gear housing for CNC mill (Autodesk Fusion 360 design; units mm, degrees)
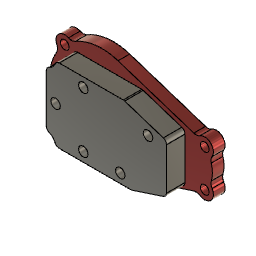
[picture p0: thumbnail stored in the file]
description: Gear Housing Assembly
derived_base_feature "Derived Base Feature1"
derived_base_feature "Derived Base Feature1" bodies "Front Housing"
derived_base_feature "Derived Base Feature1" bodies "Front Cover"
derived_base_feature "Derived Base Feature1" bodies "Back Housing"
as_built_joint "As-built1"
offset_faces "OffsetFaces1" distance 5
delete_face "DeleteFace1"
delete_face "DeleteFace2"
sketch "Sketch1" plane through (0, -21, 0) normal (0, -1, 0) x axis (1, 0, 0)
  line L1 (11.1724, 34.2225) -> (63.2283, 17.2281)
  line L2 (63.2283, -17.2281) -> (11.1724, -34.2225)
  arc A1 centre (64.7801, 21.9812) radius 5 clockwise from (67.4836, 17.7752) to (63.2283, 17.2281)
  arc A2 centre (0, 0) radius 36 clockwise from (-18.189, 31.067) to (11.1724, 34.2225)
  arc A3 centre (-20.7152, 35.3819) radius 5 clockwise from (-18.189, 31.067) to (-22.8701, 30.8701)
  arc A4 centre (-25.4558, 25.4558) radius 6 clockwise from (-30.8701, 22.8701) to (-22.8701, 30.8701)
  arc A5 centre (-35.3819, 20.7152) radius 5 clockwise from (-30.8701, 22.8701) to (-31.067, 18.189)
  arc A6 centre (0, 0) radius 36 clockwise from (-31.067, -18.189) to (-31.067, 18.189)
  arc A7 centre (-35.3819, -20.7152) radius 5 clockwise from (-31.067, -18.189) to (-30.8701, -22.8701)
  arc A8 centre (-25.4558, -25.4558) radius 6 clockwise from (-22.8701, -30.8701) to (-30.8701, -22.8701)
  arc A9 centre (-20.7152, -35.3819) radius 5 clockwise from (-22.8701, -30.8701) to (-18.189, -31.067)
  arc A10 centre (0, 0) radius 36 clockwise from (11.1724, -34.2225) to (-18.189, -31.067)
  arc A11 centre (64.7801, -21.9812) radius 5 clockwise from (63.2283, -17.2281) to (67.4836, -17.7752)
  arc A12 centre (70.7279, -12.7279) radius 6 clockwise from (75.774, -9.4818) to (67.4836, -17.7752)
  arc A13 centre (79.979, -6.7767) radius 5 clockwise from (75.774, -9.4818) to (75.201, -5.3035)
  arc A14 centre (58, 0) radius 18 clockwise from (75.201, 5.3035) to (75.201, -5.3035)
  arc A15 centre (79.979, 6.7767) radius 5 clockwise from (75.201, 5.3035) to (75.774, 9.4818)
  arc A16 centre (70.7279, 12.7279) radius 6 clockwise from (67.4836, 17.7752) to (75.774, 9.4818)
  circle C1 centre (70.7279, -12.7279) radius 3
  circle C2 centre (70.7279, 12.7279) radius 3
  circle C3 centre (-25.4558, -25.4558) radius 3
  circle C4 centre (-25.4558, 25.4558) radius 3
  circle C5 centre (0, 0) radius 5.25
  circle C6 centre (0, 0) radius 19.05
  point P1 (0, 0)
  point P34 (0, 0)
  point P35 (0, -19.05)
  point P36 (-19.05, 0)
  point P37 (0, 19.05)
  point P38 (44.45, 12.7)
  point P39 (25.4, -19.05)
  coincident P1 P34
  coincident C6 P35
  coincident C6 P36
  coincident C6 P37
  vertical P34 P35
  horizontal P1 P36
  vertical P1 P37
  dimension "d2" diameter C6 = 38.1
  dimension "d3" distance P1 P38 = 44.45
  dimension "d4" distance P1 P38 = 12.7
  dimension "d5" distance P34 P39 = 25.4
  dimension "d6" distance P34 P39 = 19.05
hole "Hole1" HoleDepth 5.715 HoleDiameter 5.1308 TipAngle 118
ground "Ground1"
ground "Ground2"
ground "Ground3"
ground "Ground4"
position "Position1"
sketch "Sketch1" plane through (0, 0, 0) normal (0, 1, 0) x axis (1, 0, 0)
  line L1 (57.15, -25.4) -> (-25.4, -25.4)
  line L2 (57.15, 25.4) -> (57.15, -25.4)
  line L3 (-25.4, 25.4) -> (57.15, 25.4)
  line L4 (-25.4, -25.4) -> (-25.4, 25.4)
  line L5 (11.1724, -34.2225) -> (63.2283, -17.2281)
  line L6 (63.2283, 17.2281) -> (11.1724, 34.2225)
  line L7 (10.1871, -31.2042) -> (62.243, -14.2098)
  line L8 (62.7357, 15.719) -> (10.6797, 32.7134)
  circle C1 centre (-25.4558, -25.4558) radius 3
  circle C2 centre (-25.4558, 25.4558) radius 3
  circle C3 centre (-25.4558, -25.4558) radius 6.35
  circle C4 centre (-25.4558, 25.4558) radius 6.35
  point P1 (0, 0)
  horizontal L1
  vertical L2
  horizontal L3
  vertical L4
  concentric C1 C3
  concentric C2 C4
  equal C3 C4
  dimension "d10" distance P1 L1 = 25.4
  dimension "d11" distance P1 L3 = 25.4 (= "d10")
  dimension "d12" distance P1 L2 = 57.15
  dimension "d13" distance P1 L4 = 25.4
  dimension "d14" diameter C3 = 12.7
  dimension "d15" = 3.175
  dimension "d16" = 1.5875
extrude "Extrude1" new body sketch "Sketch1" profile of L1 L2 L3 L4 C3 C4 L7 L8 against normal blind 12.7
fillet "Fillet1" radius 3.175
hole "Hole1" HoleDepth 12.7 HoleDiameter 6.477 TipAngle 118
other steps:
thread "Thread1"
create_component "CreateComponent1"
create_component "CreateComponent5"
create_component "CreateComponent1"
create_component "CreateComponent2"
create_component "CreateComponent3"
named bodies: "Back Housing", "Front Cover", "Front Housing"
